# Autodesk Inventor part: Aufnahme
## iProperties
Created: 2007-01
Part Number: Aufnahme
Document SubType Name: Modeling
Designer: Kumpf
Manufacturer: Standard
Standards Organization: Custom
Author: Kumpf
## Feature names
1. Drehung1 [Revolution]
2. Rundung1 [Fillet]
3. Fase1 [Chamfer]
